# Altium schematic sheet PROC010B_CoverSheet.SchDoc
size 431 x 279 mm; Date: Not shown in title block; ApprovedBy: Not shown in title block; CheckedBy: Not shown in title block; Author: Not shown in title block; CompanyName: Not shown in title block; DrawnBy: Adrian Ozer; Engineer: Not shown in title block; Organization: Not shown in title block; Address1: Not shown in title block; Address2: Not shown in title block; Address3: Not shown in title block; Address4: Not shown in title block; DocumentNumber: 1; Revision: Use project parameter SCH_Rev; SheetNumber: 1; SheetTotal: 16; PageSetup: Record=PageOptions¦CenterHorizontal=True¦CenterVertical=True¦PrintScale=1.00¦XCorrection=1.00¦YCorrection=1.00¦PrintKind=0¦BorderSize=5000000¦LeftOffset=0¦BottomOffset=0¦Orientation=2¦PaperLength=1000¦PaperWidth=1000¦Scale=100¦PaperSource=15¦PrintQuality=600¦MediaType=1¦DitherType=10¦PaperKind=Letter¦PrintScaleMode=1
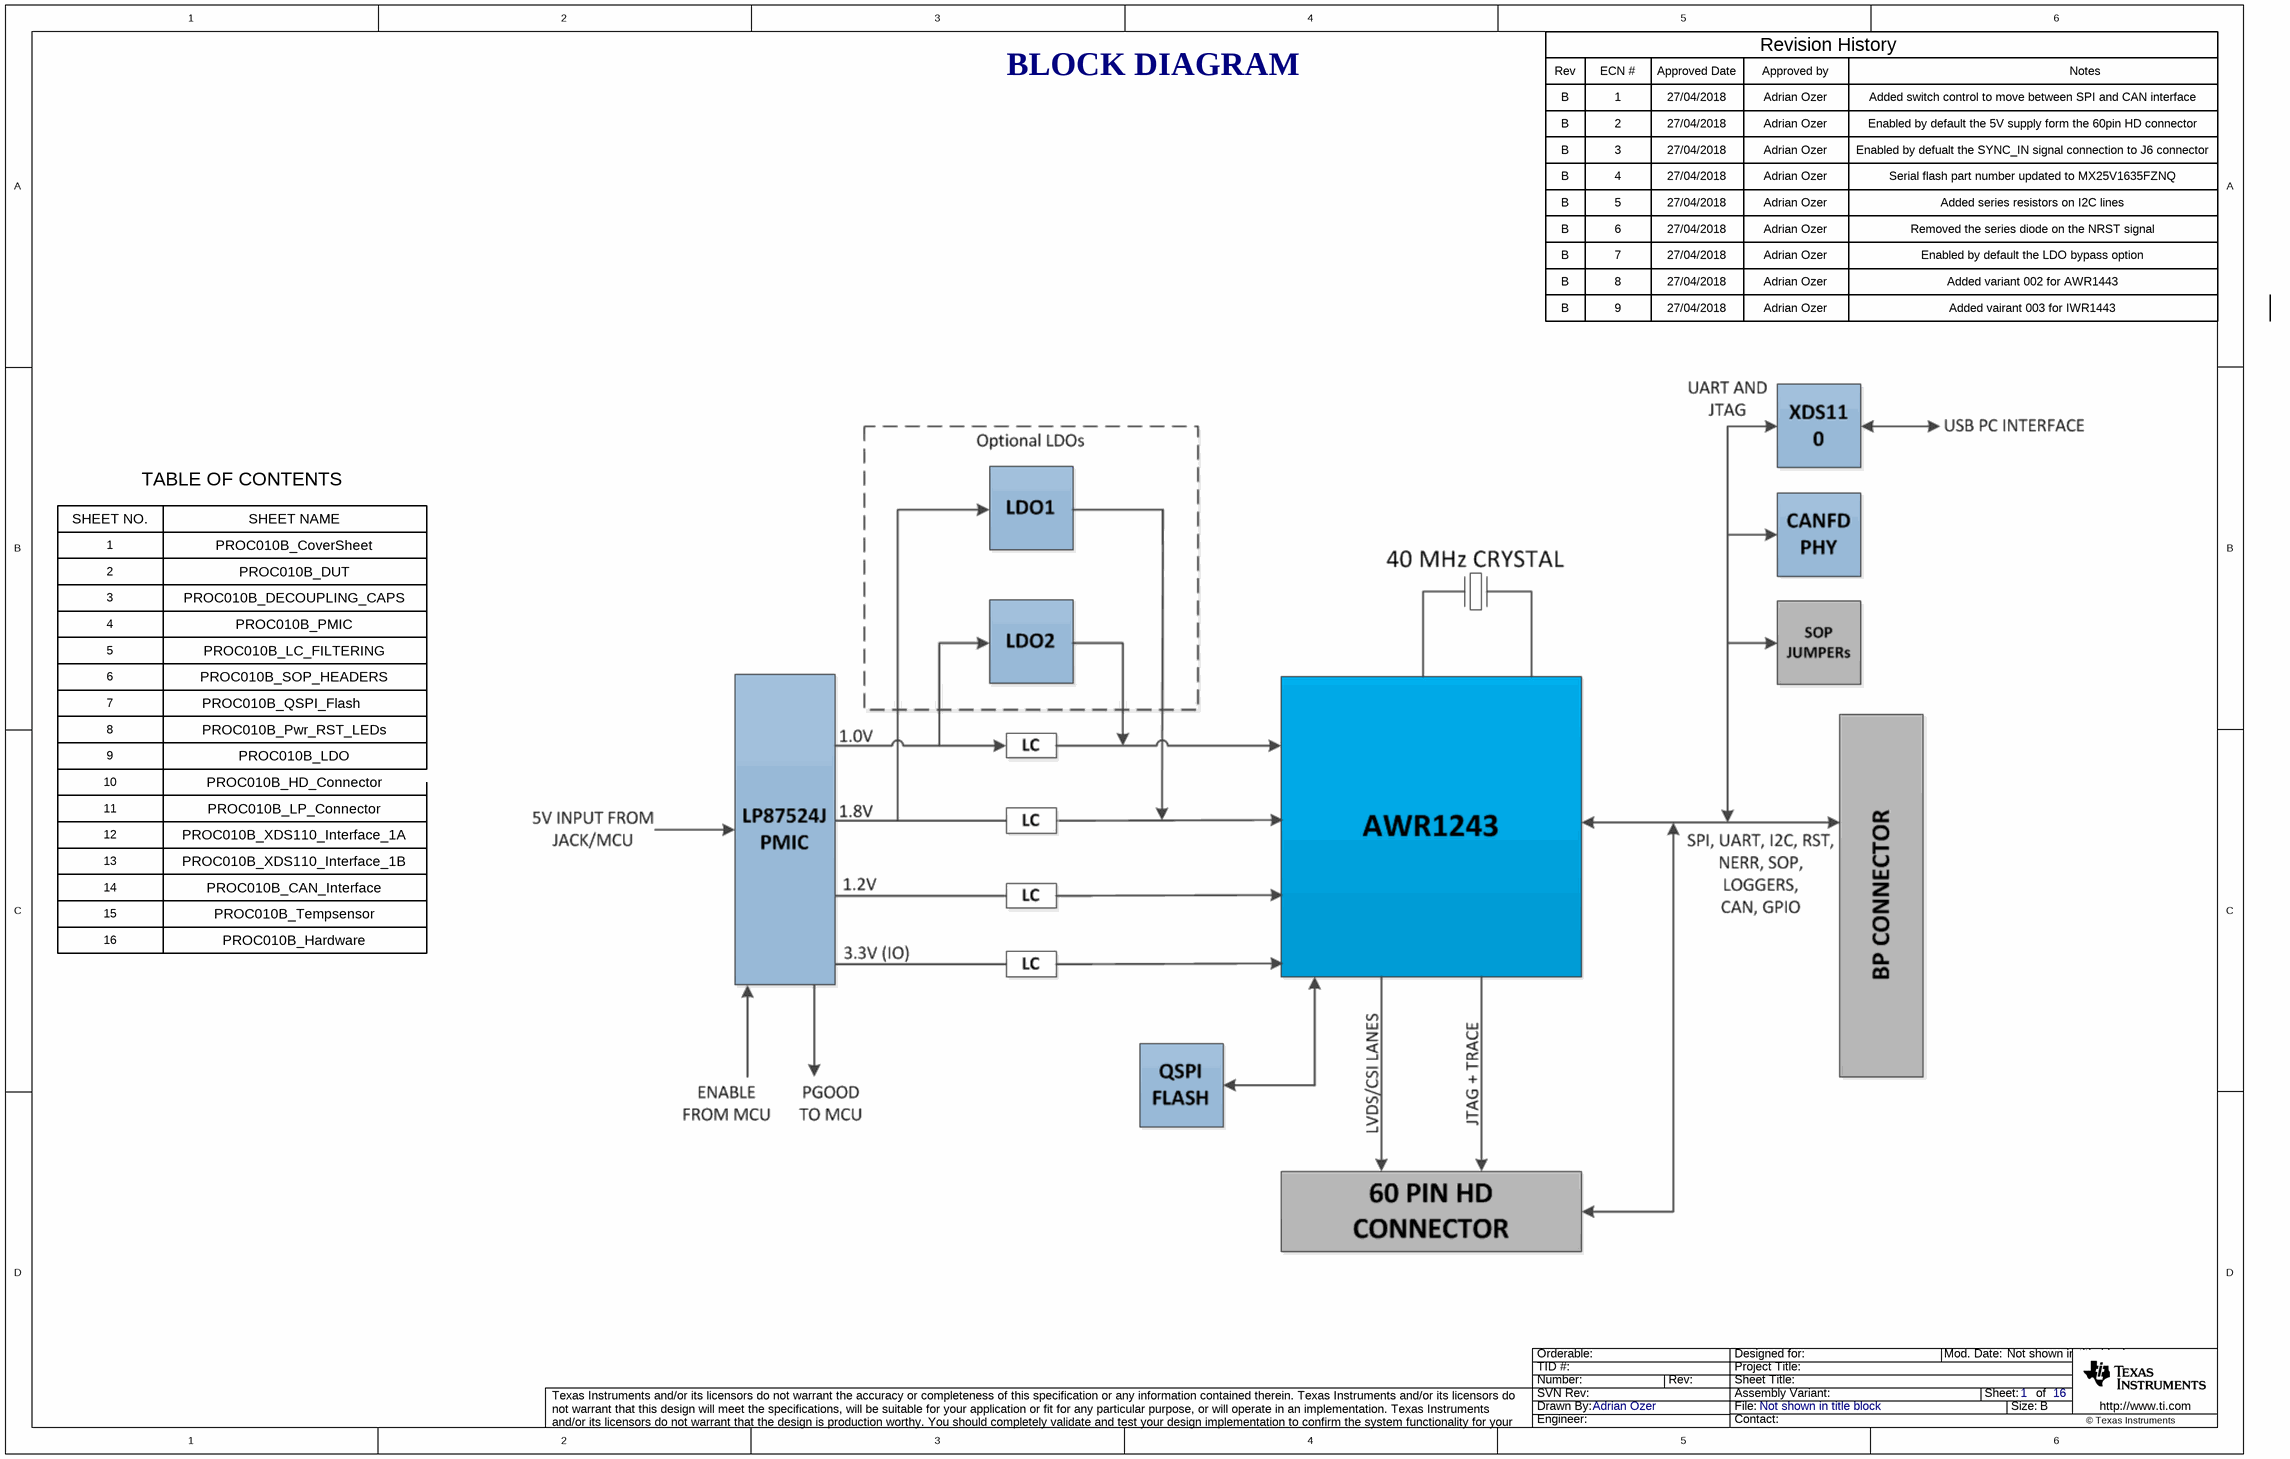
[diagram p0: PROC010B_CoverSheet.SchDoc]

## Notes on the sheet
- BLOCK DIAGRAM
- Rev
- B
- ECN #
- 1
- Approved Date
- 27/04/2018
- Approved by
- Adrian Ozer
- Revision History
- Added switch control to move between SPI and CAN interface
- Notes
- 2
- 3
- Enabled by default the 5V supply form the 60pin HD connector
- Enabled by defualt the SYNC_IN signal connection to J6 connector
- 4
- 5
- 6
- Serial flash part number updated to MX25V1635FZNQ
- Added series resistors on I2C lines
- Removed the series diode on the NRST signal
- 7
- 8
- Enabled by default the LDO bypass option
- Added variant 002 for AWR1443
- 9
- Added vairant 003 for IWR1443
- TABLE OF CONTENTS
- SHEET NO.
- SHEET NAME
- PROC010B_CoverSheet
- PROC010B_DUT
- PROC010B_DECOUPLING_CAPS
- PROC010B_PMIC
- PROC010B_LC_FILTERING
- PROC010B_SOP_HEADERS
- PROC010B_QSPI_Flash
- PROC010B_Pwr_RST_LEDs
- PROC010B_LDO
- 11
- 10
- PROC010B_HD_Connector
- PROC010B_LP_Connector
- 12
- 13
- 14
- PROC010B_XDS110_Interface_1A
- PROC010B_XDS110_Interface_1B
- PROC010B_CAN_Interface
- 15
- 16
- PROC010B_Tempsensor
- PROC010B_Hardware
